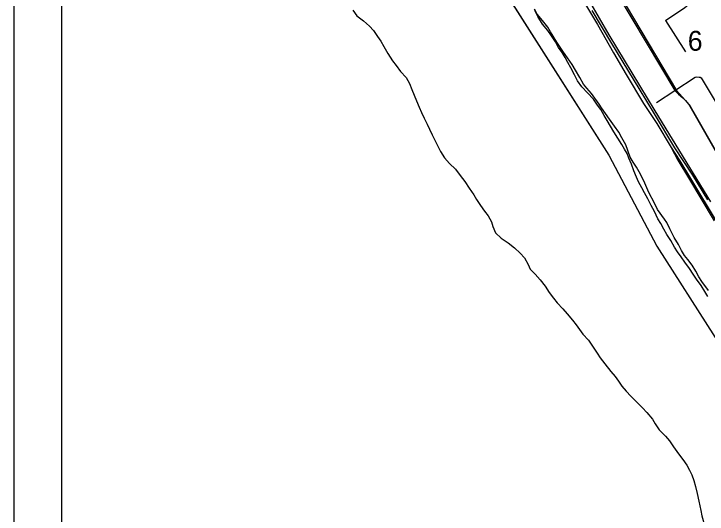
# Model space of a CAD drawing. Extents: x 0 to 34, y 0 to 22.
# Drawn here: x 2 to 3.46, y 16.365 to 17.418 of the extents above; entities that cross this region are included whole.
import ezdxf

# ---------------------------------------------------------------- set-up
doc = ezdxf.new("R2010")
doc.units = 0
for name, color, linetype in [('GM_X_City_Street', 7, 'Continuous'), ('GM_X_Corporation', 7, 'Continuous'), ('GM_X_County_Road', 7, 'Continuous'), ('GM_X_Major_River', 7, 'Continuous'), ('GM_X_Rail_Line', 7, 'Continuous'), ('GM_X_Section_Text', 7, 'Continuous'), ('GM_X_US_Route', 7, 'Continuous'), ('SH_Data', 7, 'Continuous')]:
    doc.layers.add(name, color=color, linetype=linetype)

msp = doc.modelspace()

# ---------------------------------------------------------------- linework, layer by layer
at = {"layer": 'GM_X_City_Street'}
msp.add_line((3.3718, 17.4041), (3.4138, 17.3378), dxfattribs=at)
for points in [[(3.3718, 17.4041), (3.4124, 17.4317), (3.4198, 17.4367), (3.4757, 17.4747)], [(3.3532, 17.2316), (3.3916, 17.2566), (3.4348, 17.2848), (3.4377, 17.2852), (3.4432, 17.285)], [(3.4432, 17.285), (3.4453, 17.2847), (3.4469, 17.2834), (3.466, 17.2519), (3.5042, 17.1888), (3.5412, 17.1277), (3.5791, 17.0651), (3.5845, 17.0563), (3.6148, 17.0061), (3.6559, 16.9382), (3.6953, 16.8731), (3.7344, 16.8086)]]:
    msp.add_lwpolyline(points, dxfattribs=at)
at = {"layer": 'GM_X_Corporation'}
for points in [[(8.9, 20.9), (2.1, 20.9), (2.1, 18.7697), (2.2164, 18.6603), (2.3024, 18.5638), (2.4531, 18.3722), (2.5091, 18.2757), (2.5944, 18.157), (2.6477, 18.0827), (2.8129, 17.7895), (2.9482, 17.5994), (3.2529, 17.1208), (3.3535, 16.9293), (3.4766, 16.7367)], [(2.9482, 17.5994), (3.2529, 17.1208), (3.3535, 16.9293), (3.4766, 16.7367)], [(2.9482, 17.5993), (3.2529, 17.1208), (3.3535, 16.9293), (3.4766, 16.7367)], [(3.4623, 16.8355), (3.4483, 16.8547), (3.4421, 16.8644), (3.4356, 16.8763), (3.4283, 16.8893), (3.4192, 16.9013), (3.4118, 16.9094), (3.4056, 16.9202), (3.3991, 16.9328), (3.39, 16.9475), (3.3809, 16.9655), (3.3748, 16.9785), (3.3697, 16.9858), (3.3554, 17.0062), (3.3485, 17.0193), (3.3366, 17.0423), (3.3284, 17.0618), (3.3197, 17.0806), (3.311, 17.0952), (3.304, 17.106), (3.2979, 17.1164), (3.2883, 17.1424), (3.2799, 17.1573), (3.2734, 17.1693), (3.2646, 17.1816), (3.2543, 17.1962), (3.2371, 17.2201), (3.2324, 17.2282), (3.2163, 17.2502), (3.2067, 17.2618), (3.1997, 17.2703), (3.1913, 17.2838), (3.1826, 17.2995), (3.1753, 17.3114), (3.1658, 17.3257), (3.1574, 17.3373), (3.1435, 17.3584), (3.1296, 17.38), (3.1246, 17.3899), (3.1132, 17.4039), (3.1017, 17.417), (3.0959, 17.4278)]]:
    msp.add_lwpolyline(points, dxfattribs=at)
at = {"layer": 'GM_X_County_Road'}
for points in [[(3.112, 17.7916), (3.1305, 17.7554), (3.1449, 17.7124), (3.1653, 17.671), (3.1775, 17.6407), (3.2177, 17.5553), (3.2275, 17.5328), (3.2411, 17.5098), (3.3916, 17.2566), (3.3995, 17.2491), (3.4084, 17.2414), (3.4144, 17.2355), (3.424, 17.224), (3.4374, 17.2005), (3.4403, 17.1954)], [(3.4403, 17.1954), (3.4599, 17.1612), (3.4955, 17.0991), (3.5317, 17.0358), (3.5663, 16.9763), (3.6066, 16.9069), (3.6432, 16.8438), (3.6835, 16.7746), (3.6969, 16.7516), (3.713, 16.7258), (3.7609, 16.6611), (3.7657, 16.655), (3.7823, 16.6344), (3.804, 16.6055), (3.846, 16.5432), (3.887, 16.4854), (3.8904, 16.4808), (3.9025, 16.4638), (3.9229, 16.4395), (3.9444, 16.4189), (3.95, 16.4142), (3.9523, 16.4123)]]:
    msp.add_lwpolyline(points, dxfattribs=at)
at = {"layer": 'GM_X_Major_River'}
for points in [[(2.714, 17.426), (2.7221, 17.4137), (2.736, 17.4032), (2.7491, 17.3924), (2.7573, 17.3828), (2.7658, 17.3705), (2.7725, 17.3605), (2.7788, 17.3494), (2.7873, 17.3345), (2.7969, 17.3191), (2.8051, 17.3091), (2.8144, 17.2968), (2.8259, 17.2837), (2.8329, 17.2711), (2.8381, 17.2585), (2.8428, 17.247), (2.8479, 17.2352), (2.8534, 17.2218), (2.8582, 17.2103), (2.864, 17.1985), (2.8703, 17.1855), (2.8754, 17.1755), (2.8809, 17.1633), (2.8853, 17.1537), (2.8923, 17.1407), (2.8986, 17.1281), (2.9067, 17.1147), (2.9172, 17.1031), (2.9299, 17.0912), (2.9399, 17.0781), (2.9496, 17.0654), (2.9588, 17.0512), (2.9681, 17.037), (2.974, 17.0271), (2.9822, 17.0148), (2.9911, 17.0029), (2.9989, 16.9929), (3.0059, 16.9799), (3.0084, 16.9703), (3.0143, 16.9573), (3.0262, 16.9461), (3.0408, 16.9357), (3.054, 16.9252), (3.0659, 16.9144), (3.0749, 16.9044), (3.0826, 16.8906), (3.087, 16.8806), (3.0975, 16.8702), (3.1083, 16.8579), (3.1183, 16.8445), (3.1268, 16.8318), (3.1361, 16.8195), (3.1439, 16.8095), (3.1559, 16.7968), (3.1652, 16.7864), (3.176, 16.7733), (3.1838, 16.7633), (3.1912, 16.7537), (3.1979, 16.7441), (3.2102, 16.731), (3.2213, 16.7142), (3.228, 16.7038), (3.2347, 16.6938), (3.2443, 16.6815), (3.2566, 16.6654), (3.2663, 16.6546), (3.273, 16.6446), (3.28, 16.6347), (3.289, 16.6239), (3.2987, 16.6135), (3.3117, 16.6008), (3.3233, 16.5888), (3.333, 16.5792), (3.3445, 16.5649)], [(3.4613, 16.8231), (3.455, 16.8338), (3.4472, 16.8465), (3.4372, 16.8599), (3.4301, 16.8699), (3.4224, 16.8818), (3.4127, 16.8956), (3.4053, 16.9064), (3.3975, 16.9171), (3.3912, 16.9271), (3.3831, 16.9409), (3.3746, 16.9539), (3.3687, 16.9647), (3.3624, 16.9765), (3.3557, 16.9869), (3.3488, 17.0022), (3.3421, 17.0148), (3.3348, 17.0286), (3.3278, 17.0416), (3.3219, 17.0516), (3.3149, 17.0646), (3.3108, 17.0741), (3.305, 17.0879), (3.3003, 17.1013), (3.2951, 17.1139), (3.2911, 17.1238), (3.286, 17.1334), (3.2804, 17.1429), (3.2719, 17.156), (3.2634, 17.1694), (3.2494, 17.1932), (3.2427, 17.2039), (3.2357, 17.2165), (3.229, 17.2261), (3.2201, 17.2384), (3.2078, 17.2515), (3.1959, 17.2642), (3.1869, 17.2769), (3.1807, 17.2899), (3.173, 17.3045), (3.1667, 17.3156), (3.1604, 17.3263), (3.1541, 17.3366), (3.1467, 17.3474), (3.1405, 17.3592), (3.1319, 17.3719), (3.1241, 17.3827), (3.1133, 17.3965), (3.1034, 17.4122), (3.0971, 17.4252)], [(3.3445, 16.5649), (3.3505, 16.5553), (3.359, 16.5427), (3.3721, 16.5292), (3.3802, 16.5192), (3.3888, 16.5065), (3.3995, 16.4916), (3.4085, 16.48), (3.417, 16.4678), (3.4225, 16.4578), (3.4273, 16.4479), (3.432, 16.436), (3.4349, 16.4234), (3.4388, 16.4082), (3.4423, 16.3922), (3.4445, 16.3827), (3.4462, 16.3724), (3.4483, 16.3614), (3.4512, 16.3514), (3.4551, 16.3351), (3.4591, 16.3236), (3.4635, 16.3133)]]:
    msp.add_lwpolyline(points, dxfattribs=at)
at = {"layer": 'GM_X_Rail_Line'}
for points in [[(2.1, 18.9805), (2.1848, 18.9497), (2.3592, 18.8383), (2.5014, 18.7513), (2.6158, 18.6907), (2.7269, 18.6312), (2.7893, 18.6123), (2.8663, 18.5659), (2.9659, 18.5014), (3.0581, 18.4349), (3.118, 18.3921), (3.1299, 18.3322), (3.1312, 18.287), (3.0912, 18.2088), (3.028, 18.1378), (3.0132, 18.0857), (3.0138, 18.0431), (3.0154, 18.0122), (3.102, 17.8167), (3.2006, 17.5845), (3.3952, 17.257), (3.4206, 17.2288), (3.4993, 17.0909)], [(3.1814, 17.4756), (3.2287, 17.3954), (3.2625, 17.3362), (3.2893, 17.2906), (3.3255, 17.2294), (3.3536, 17.1869), (3.3838, 17.1365), (3.4023, 17.1084), (3.4244, 17.0713), (3.4787, 16.9817)], [(3.2171, 17.4251), (3.258, 17.3553), (3.3156, 17.2606), (3.348, 17.2078), (3.391, 17.1363), (3.4287, 17.0786), (3.4607, 17.0265)], [(3.3838, 17.1365), (3.3847, 17.1351), (3.3983, 17.1099), (3.4206, 17.0725), (3.4747, 16.9821)]]:
    msp.add_lwpolyline(points, dxfattribs=at)
at = {"layer": 'GM_X_US_Route'}
msp.add_lwpolyline([(2.8233, 18.2456), (2.8261, 18.2362), (2.8285, 18.2268), (2.8311, 18.2165), (2.8524, 18.1327), (2.8706, 18.0673), (2.8904, 18.0217), (2.9182, 17.9652), (2.9532, 17.9025), (2.9747, 17.8697), (3.0247, 17.7877), (3.0554, 17.7182), (3.1193, 17.6003), (3.1915, 17.4797), (3.253, 17.3737), (3.3492, 17.2141), (3.4666, 17.0225)], dxfattribs=at)
at = {"layer": 'SH_Data'}
for p, q in [((2, 21), (2, 14)), ((2.1, 20.9), (2.1, 14.1))]:
    msp.add_line(p, q, dxfattribs=at)

# ---------------------------------------------------------------- texts
at = {"layer": 'GM_X_Section_Text'}
msp.add_text('6', height=0.0419, rotation=0, dxfattribs=at).set_placement((3.4189, 17.3403))

doc.saveas('drawing.dxf')
